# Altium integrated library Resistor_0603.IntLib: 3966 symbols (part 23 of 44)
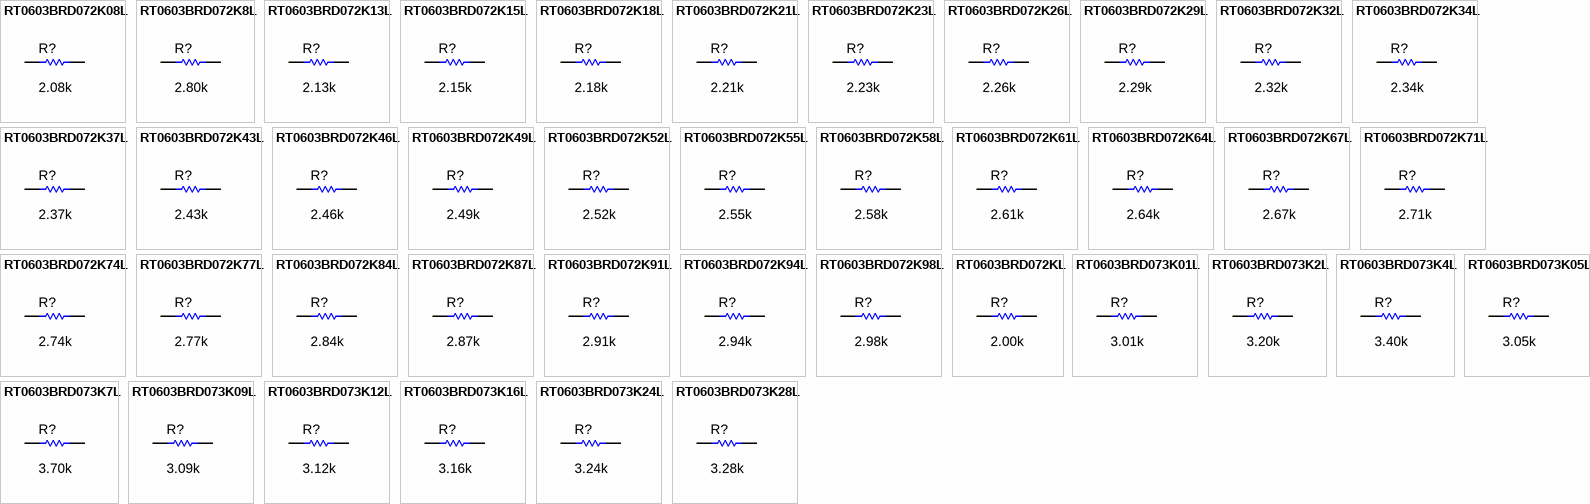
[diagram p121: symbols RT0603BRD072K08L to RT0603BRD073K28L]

## RT0603BRD072K98L
designator R?  ValueDisplayed: 2.98k  (hidden comment: RT0603BRD072K98L)
RES, 2.98 k, 0.1%, 0.1 W, 0603; Manufacturer: Yageo America; CompType: Resistor; Value: 2.98k; Res_ohm: 2980; Value_Code: 2k98; Tolerance_%: 0.1; Value2: 0.1W; VDC_V: 75; TempCo: 25 ppm/C; SizeArea_mm2: 1.28; SizeX_mm: 1.6; SizeY_mm: 0.8; SizeZ_mm: 1; EIA_Code: E192; U/M: EA; AEC Category: Q200
signal-integrity model Resistor
simulation model Resistor
footprint 0603
footprint 0603M
footprint 0603L
footprint 0603_HV
footprint 0603S
pins: 1, 2

## RT0603BRD072KL
designator R?  ValueDisplayed: 2.00k  (hidden comment: RT0603BRD072KL)
RES, 2.00 k, 0.1%, 0.1 W, 0603; Manufacturer: Yageo America; CompType: Resistor; Value: 2.00k; Res_ohm: 2000; Value_Code: 2k00; Tolerance_%: 0.1; Value2: 0.1W; VDC_V: 75; TempCo: 25 ppm/C; SizeArea_mm2: 1.28; SizeX_mm: 1.6; SizeY_mm: 0.8; SizeZ_mm: 1; EIA_Code: E192; U/M: EA; AEC Category: Q200
signal-integrity model Resistor
simulation model Resistor
footprint 0603
footprint 0603M
footprint 0603L
footprint 0603_HV
footprint 0603S
pins: 1, 2

## RT0603BRD073K01L
designator R?  ValueDisplayed: 3.01k  (hidden comment: RT0603BRD073K01L)
RES, 3.01 k, 0.1%, 0.1 W, 0603; Manufacturer: Yageo America; CompType: Resistor; Value: 3.01k; Res_ohm: 3010; Value_Code: 3k01; Tolerance_%: 0.1; Value2: 0.1W; VDC_V: 75; TempCo: 25 ppm/C; SizeArea_mm2: 1.28; SizeX_mm: 1.6; SizeY_mm: 0.8; SizeZ_mm: 1; EIA_Code: E192; U/M: EA; AEC Category: Q200; Green_Lifecycle: Active; Green_REACh: Passed
signal-integrity model Resistor
simulation model Resistor
footprint 0603
footprint 0603M
footprint 0603L
footprint 0603_HV
footprint 0603S
pins: 1, 2

## RT0603BRD073K2L
designator R?  ValueDisplayed: 3.20k  (hidden comment: RT0603BRD073K2L)
RES, 3.20 k, 0.1%, 0.1 W, 0603; Manufacturer: Yageo America; CompType: Resistor; Value: 3.20k; Res_ohm: 3200; Value_Code: 3k20; Tolerance_%: 0.1; Value2: 0.1W; VDC_V: 75; TempCo: 25 ppm/C; SizeArea_mm2: 1.28; SizeX_mm: 1.6; SizeY_mm: 0.8; SizeZ_mm: 1; EIA_Code: E192; U/M: EA; AEC Category: Q200
signal-integrity model Resistor
simulation model Resistor
footprint 0603
footprint 0603M
footprint 0603L
footprint 0603_HV
footprint 0603S
pins: 1, 2

## RT0603BRD073K4L
designator R?  ValueDisplayed: 3.40k  (hidden comment: RT0603BRD073K4L)
RES, 3.40 k, 0.1%, 0.1 W, 0603; Manufacturer: Yageo America; CompType: Resistor; Value: 3.40k; Res_ohm: 3400; Value_Code: 3k40; Tolerance_%: 0.1; Value2: 0.1W; VDC_V: 75; TempCo: 25 ppm/C; SizeArea_mm2: 1.28; SizeX_mm: 1.6; SizeY_mm: 0.8; SizeZ_mm: 1; EIA_Code: E192; U/M: EA; AEC Category: Q200
signal-integrity model Resistor
simulation model Resistor
footprint 0603
footprint 0603M
footprint 0603L
footprint 0603_HV
footprint 0603S
pins: 1, 2

## RT0603BRD073K05L
designator R?  ValueDisplayed: 3.05k  (hidden comment: RT0603BRD073K05L)
RES, 3.05 k, 0.1%, 0.1 W, 0603; Manufacturer: Yageo America; CompType: Resistor; Value: 3.05k; Res_ohm: 3050; Value_Code: 3k05; Tolerance_%: 0.1; Value2: 0.1W; VDC_V: 75; TempCo: 25 ppm/C; SizeArea_mm2: 1.28; SizeX_mm: 1.6; SizeY_mm: 0.8; SizeZ_mm: 1; EIA_Code: E192; U/M: EA; AEC Category: Q200
signal-integrity model Resistor
simulation model Resistor
footprint 0603
footprint 0603M
footprint 0603L
footprint 0603_HV
footprint 0603S
pins: 1, 2

## RT0603BRD073K7L
designator R?  ValueDisplayed: 3.70k  (hidden comment: RT0603BRD073K7L)
RES, 3.70 k, 0.1%, 0.1 W, 0603; Manufacturer: Yageo America; CompType: Resistor; Value: 3.70k; Res_ohm: 3700; Value_Code: 3k70; Tolerance_%: 0.1; Value2: 0.1W; VDC_V: 75; TempCo: 25 ppm/C; SizeArea_mm2: 1.28; SizeX_mm: 1.6; SizeY_mm: 0.8; SizeZ_mm: 1; EIA_Code: E192; U/M: EA; AEC Category: Q200
signal-integrity model Resistor
simulation model Resistor
footprint 0603
footprint 0603M
footprint 0603L
footprint 0603_HV
footprint 0603S
pins: 1, 2

## RT0603BRD073K09L
designator R?  ValueDisplayed: 3.09k  (hidden comment: RT0603BRD073K09L)
RES, 3.09 k, 0.1%, 0.1 W, 0603; Manufacturer: Yageo America; CompType: Resistor; Value: 3.09k; Res_ohm: 3090; Value_Code: 3k09; Tolerance_%: 0.1; Value2: 0.1W; VDC_V: 75; TempCo: 25 ppm/C; SizeArea_mm2: 1.28; SizeX_mm: 1.6; SizeY_mm: 0.8; SizeZ_mm: 1; EIA_Code: E192; U/M: EA; AEC Category: Q200
signal-integrity model Resistor
simulation model Resistor
footprint 0603
footprint 0603M
footprint 0603L
footprint 0603_HV
footprint 0603S
pins: 1, 2

## RT0603BRD073K12L
designator R?  ValueDisplayed: 3.12k  (hidden comment: RT0603BRD073K12L)
RES, 3.12 k, 0.1%, 0.1 W, 0603; Manufacturer: Yageo America; CompType: Resistor; Value: 3.12k; Res_ohm: 3120; Value_Code: 3k12; Tolerance_%: 0.1; Value2: 0.1W; VDC_V: 75; TempCo: 25 ppm/C; SizeArea_mm2: 1.28; SizeX_mm: 1.6; SizeY_mm: 0.8; SizeZ_mm: 1; EIA_Code: E192; U/M: EA; AEC Category: Q200
signal-integrity model Resistor
simulation model Resistor
footprint 0603
footprint 0603M
footprint 0603L
footprint 0603_HV
footprint 0603S
pins: 1, 2

## RT0603BRD073K16L
designator R?  ValueDisplayed: 3.16k  (hidden comment: RT0603BRD073K16L)
RES, 3.16 k, 0.1%, 0.1 W, 0603; Manufacturer: Yageo America; CompType: Resistor; Value: 3.16k; Res_ohm: 3160; Value_Code: 3k16; Tolerance_%: 0.1; Value2: 0.1W; VDC_V: 75; TempCo: 25 ppm/C; SizeArea_mm2: 1.28; SizeX_mm: 1.6; SizeY_mm: 0.8; SizeZ_mm: 1; EIA_Code: E192; U/M: EA; AEC Category: Q200
signal-integrity model Resistor
simulation model Resistor
footprint 0603
footprint 0603M
footprint 0603L
footprint 0603_HV
footprint 0603S
pins: 1, 2

## RT0603BRD073K24L
designator R?  ValueDisplayed: 3.24k  (hidden comment: RT0603BRD073K24L)
RES, 3.24 k, 0.1%, 0.1 W, 0603; Manufacturer: Yageo America; CompType: Resistor; Value: 3.24k; Res_ohm: 3240; Value_Code: 3k24; Tolerance_%: 0.1; Value2: 0.1W; VDC_V: 75; TempCo: 25 ppm/C; SizeArea_mm2: 1.28; SizeX_mm: 1.6; SizeY_mm: 0.8; SizeZ_mm: 1; EIA_Code: E192; U/M: EA; AEC Category: Q200
signal-integrity model Resistor
simulation model Resistor
footprint 0603
footprint 0603M
footprint 0603L
footprint 0603_HV
footprint 0603S
pins: 1, 2

## RT0603BRD073K28L
designator R?  ValueDisplayed: 3.28k  (hidden comment: RT0603BRD073K28L)
RES, 3.28 k, 0.1%, 0.1 W, 0603; Manufacturer: Yageo America; CompType: Resistor; Value: 3.28k; Res_ohm: 3280; Value_Code: 3k28; Tolerance_%: 0.1; Value2: 0.1W; VDC_V: 75; TempCo: 25 ppm/C; SizeArea_mm2: 1.28; SizeX_mm: 1.6; SizeY_mm: 0.8; SizeZ_mm: 1; EIA_Code: E192; U/M: EA; AEC Category: Q200
signal-integrity model Resistor
simulation model Resistor
footprint 0603
footprint 0603M
footprint 0603L
footprint 0603_HV
footprint 0603S
pins: 1, 2

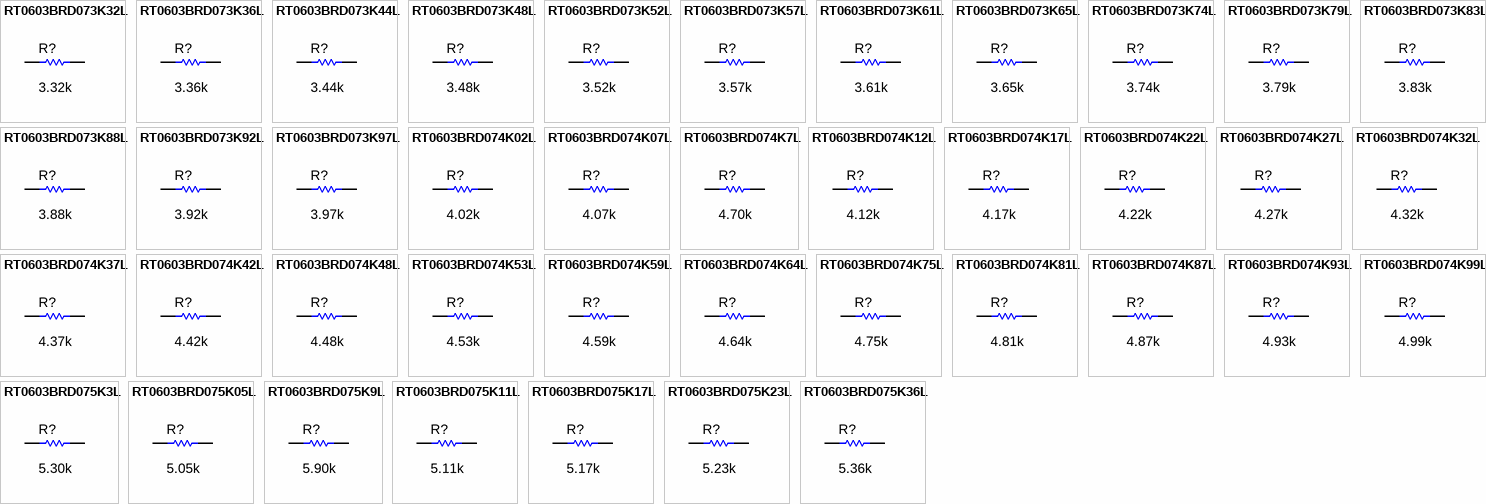
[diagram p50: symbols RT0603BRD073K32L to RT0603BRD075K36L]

## RT0603BRD073K32L
designator R?  ValueDisplayed: 3.32k  (hidden comment: RT0603BRD073K32L)
RES, 3.32 k, 0.1%, 0.1 W, 0603; Manufacturer: Yageo America; CompType: Resistor; Value: 3.32k; Res_ohm: 3320; Value_Code: 3k32; Tolerance_%: 0.1; Value2: 0.1W; VDC_V: 75; TempCo: 25 ppm/C; SizeArea_mm2: 1.28; SizeX_mm: 1.6; SizeY_mm: 0.8; SizeZ_mm: 1; EIA_Code: E192; U/M: EA; AEC Category: Q200
signal-integrity model Resistor
simulation model Resistor
footprint 0603
footprint 0603M
footprint 0603L
footprint 0603_HV
footprint 0603S
pins: 1, 2

## RT0603BRD073K36L
designator R?  ValueDisplayed: 3.36k  (hidden comment: RT0603BRD073K36L)
RES, 3.36 k, 0.1%, 0.1 W, 0603; Manufacturer: Yageo America; CompType: Resistor; Value: 3.36k; Res_ohm: 3360; Value_Code: 3k36; Tolerance_%: 0.1; Value2: 0.1W; VDC_V: 75; TempCo: 25 ppm/C; SizeArea_mm2: 1.28; SizeX_mm: 1.6; SizeY_mm: 0.8; SizeZ_mm: 1; EIA_Code: E192; U/M: EA; AEC Category: Q200
signal-integrity model Resistor
simulation model Resistor
footprint 0603
footprint 0603M
footprint 0603L
footprint 0603_HV
footprint 0603S
pins: 1, 2

## RT0603BRD073K44L
designator R?  ValueDisplayed: 3.44k  (hidden comment: RT0603BRD073K44L)
RES, 3.44 k, 0.1%, 0.1 W, 0603; Manufacturer: Yageo America; CompType: Resistor; Value: 3.44k; Res_ohm: 3440; Value_Code: 3k44; Tolerance_%: 0.1; Value2: 0.1W; VDC_V: 75; TempCo: 25 ppm/C; SizeArea_mm2: 1.28; SizeX_mm: 1.6; SizeY_mm: 0.8; SizeZ_mm: 1; EIA_Code: E192; U/M: EA; AEC Category: Q200
signal-integrity model Resistor
simulation model Resistor
footprint 0603
footprint 0603M
footprint 0603L
footprint 0603_HV
footprint 0603S
pins: 1, 2

## RT0603BRD073K48L
designator R?  ValueDisplayed: 3.48k  (hidden comment: RT0603BRD073K48L)
RES, 3.48 k, 0.1%, 0.1 W, 0603; Manufacturer: Yageo America; CompType: Resistor; Value: 3.48k; Res_ohm: 3480; Value_Code: 3k48; Tolerance_%: 0.1; Value2: 0.1W; VDC_V: 75; TempCo: 25 ppm/C; SizeArea_mm2: 1.28; SizeX_mm: 1.6; SizeY_mm: 0.8; SizeZ_mm: 1; EIA_Code: E192; U/M: EA; AEC Category: Q200
signal-integrity model Resistor
simulation model Resistor
footprint 0603
footprint 0603M
footprint 0603L
footprint 0603_HV
footprint 0603S
pins: 1, 2

## RT0603BRD073K52L
designator R?  ValueDisplayed: 3.52k  (hidden comment: RT0603BRD073K52L)
RES, 3.52 k, 0.1%, 0.1 W, 0603; Manufacturer: Yageo America; CompType: Resistor; Value: 3.52k; Res_ohm: 3520; Value_Code: 3k52; Tolerance_%: 0.1; Value2: 0.1W; VDC_V: 75; TempCo: 25 ppm/C; SizeArea_mm2: 1.28; SizeX_mm: 1.6; SizeY_mm: 0.8; SizeZ_mm: 1; EIA_Code: E192; U/M: EA; AEC Category: Q200
signal-integrity model Resistor
simulation model Resistor
footprint 0603
footprint 0603M
footprint 0603L
footprint 0603_HV
footprint 0603S
pins: 1, 2

## RT0603BRD073K57L
designator R?  ValueDisplayed: 3.57k  (hidden comment: RT0603BRD073K57L)
RES, 3.57 k, 0.1%, 0.1 W, 0603; Manufacturer: Yageo America; CompType: Resistor; Value: 3.57k; Res_ohm: 3570; Value_Code: 3k57; Tolerance_%: 0.1; Value2: 0.1W; VDC_V: 75; TempCo: 25 ppm/C; SizeArea_mm2: 1.28; SizeX_mm: 1.6; SizeY_mm: 0.8; SizeZ_mm: 1; EIA_Code: E192; U/M: EA; AEC Category: Q200
signal-integrity model Resistor
simulation model Resistor
footprint 0603
footprint 0603M
footprint 0603L
footprint 0603_HV
footprint 0603S
pins: 1, 2

## RT0603BRD073K61L
designator R?  ValueDisplayed: 3.61k  (hidden comment: RT0603BRD073K61L)
RES, 3.61 k, 0.1%, 0.1 W, 0603; Manufacturer: Yageo America; CompType: Resistor; Value: 3.61k; Res_ohm: 3610; Value_Code: 3k61; Tolerance_%: 0.1; Value2: 0.1W; VDC_V: 75; TempCo: 25 ppm/C; SizeArea_mm2: 1.28; SizeX_mm: 1.6; SizeY_mm: 0.8; SizeZ_mm: 1; EIA_Code: E192; U/M: EA; AEC Category: Q200
signal-integrity model Resistor
simulation model Resistor
footprint 0603
footprint 0603M
footprint 0603L
footprint 0603_HV
footprint 0603S
pins: 1, 2

## RT0603BRD073K65L
designator R?  ValueDisplayed: 3.65k  (hidden comment: RT0603BRD073K65L)
RES, 3.65 k, 0.1%, 0.1 W, 0603; Manufacturer: Yageo America; CompType: Resistor; Value: 3.65k; Res_ohm: 3650; Value_Code: 3k65; Tolerance_%: 0.1; Value2: 0.1W; VDC_V: 75; TempCo: 25 ppm/C; SizeArea_mm2: 1.28; SizeX_mm: 1.6; SizeY_mm: 0.8; SizeZ_mm: 1; EIA_Code: E192; U/M: EA; AEC Category: Q200
signal-integrity model Resistor
simulation model Resistor
footprint 0603
footprint 0603M
footprint 0603L
footprint 0603_HV
footprint 0603S
pins: 1, 2

## RT0603BRD073K74L
designator R?  ValueDisplayed: 3.74k  (hidden comment: RT0603BRD073K74L)
RES, 3.74 k, 0.1%, 0.1 W, 0603; Manufacturer: Yageo America; CompType: Resistor; Value: 3.74k; Res_ohm: 3740; Value_Code: 3k74; Tolerance_%: 0.1; Value2: 0.1W; VDC_V: 75; TempCo: 25 ppm/C; SizeArea_mm2: 1.28; SizeX_mm: 1.6; SizeY_mm: 0.8; SizeZ_mm: 1; EIA_Code: E192; U/M: EA; AEC Category: Q200
signal-integrity model Resistor
simulation model Resistor
footprint 0603
footprint 0603M
footprint 0603L
footprint 0603_HV
footprint 0603S
pins: 1, 2

## RT0603BRD073K79L
designator R?  ValueDisplayed: 3.79k  (hidden comment: RT0603BRD073K79L)
RES, 3.79 k, 0.1%, 0.1 W, 0603; Manufacturer: Yageo America; CompType: Resistor; Value: 3.79k; Res_ohm: 3790; Value_Code: 3k79; Tolerance_%: 0.1; Value2: 0.1W; VDC_V: 75; TempCo: 25 ppm/C; SizeArea_mm2: 1.28; SizeX_mm: 1.6; SizeY_mm: 0.8; SizeZ_mm: 1; EIA_Code: E192; U/M: EA; AEC Category: Q200
signal-integrity model Resistor
simulation model Resistor
footprint 0603
footprint 0603M
footprint 0603L
footprint 0603_HV
footprint 0603S
pins: 1, 2

## RT0603BRD073K83L
designator R?  ValueDisplayed: 3.83k  (hidden comment: RT0603BRD073K83L)
RES, 3.83 k, 0.1%, 0.1 W, 0603; Manufacturer: Yageo America; CompType: Resistor; Value: 3.83k; Res_ohm: 3830; Value_Code: 3k83; Tolerance_%: 0.1; Value2: 0.1W; VDC_V: 75; TempCo: 25 ppm/C; SizeArea_mm2: 1.28; SizeX_mm: 1.6; SizeY_mm: 0.8; SizeZ_mm: 1; EIA_Code: E192; U/M: EA; AEC Category: Q200
signal-integrity model Resistor
simulation model Resistor
footprint 0603
footprint 0603M
footprint 0603L
footprint 0603_HV
footprint 0603S
pins: 1, 2

## RT0603BRD073K88L
designator R?  ValueDisplayed: 3.88k  (hidden comment: RT0603BRD073K88L)
RES, 3.88 k, 0.1%, 0.1 W, 0603; Manufacturer: Yageo America; CompType: Resistor; Value: 3.88k; Res_ohm: 3880; Value_Code: 3k88; Tolerance_%: 0.1; Value2: 0.1W; VDC_V: 75; TempCo: 25 ppm/C; SizeArea_mm2: 1.28; SizeX_mm: 1.6; SizeY_mm: 0.8; SizeZ_mm: 1; EIA_Code: E192; U/M: EA; AEC Category: Q200
signal-integrity model Resistor
simulation model Resistor
footprint 0603
footprint 0603M
footprint 0603L
footprint 0603_HV
footprint 0603S
pins: 1, 2

## RT0603BRD073K92L
designator R?  ValueDisplayed: 3.92k  (hidden comment: RT0603BRD073K92L)
RES, 3.92 k, 0.1%, 0.1 W, 0603; Manufacturer: Yageo America; CompType: Resistor; Value: 3.92k; Res_ohm: 3920; Value_Code: 3k92; Tolerance_%: 0.1; Value2: 0.1W; VDC_V: 75; TempCo: 25 ppm/C; SizeArea_mm2: 1.28; SizeX_mm: 1.6; SizeY_mm: 0.8; SizeZ_mm: 1; EIA_Code: E192; U/M: EA; AEC Category: Q200
signal-integrity model Resistor
simulation model Resistor
footprint 0603
footprint 0603M
footprint 0603L
footprint 0603_HV
footprint 0603S
pins: 1, 2

## RT0603BRD073K97L
designator R?  ValueDisplayed: 3.97k  (hidden comment: RT0603BRD073K97L)
RES, 3.97 k, 0.1%, 0.1 W, 0603; Manufacturer: Yageo America; CompType: Resistor; Value: 3.97k; Res_ohm: 3970; Value_Code: 3k97; Tolerance_%: 0.1; Value2: 0.1W; VDC_V: 75; TempCo: 25 ppm/C; SizeArea_mm2: 1.28; SizeX_mm: 1.6; SizeY_mm: 0.8; SizeZ_mm: 1; EIA_Code: E192; U/M: EA; AEC Category: Q200
signal-integrity model Resistor
simulation model Resistor
footprint 0603
footprint 0603M
footprint 0603L
footprint 0603_HV
footprint 0603S
pins: 1, 2

## RT0603BRD074K02L
designator R?  ValueDisplayed: 4.02k  (hidden comment: RT0603BRD074K02L)
RES, 4.02 k, 0.1%, 0.1 W, 0603; Manufacturer: Yageo America; CompType: Resistor; Value: 4.02k; Res_ohm: 4020; Value_Code: 4k02; Tolerance_%: 0.1; Value2: 0.1W; VDC_V: 75; TempCo: 25 ppm/C; SizeArea_mm2: 1.28; SizeX_mm: 1.6; SizeY_mm: 0.8; SizeZ_mm: 1; EIA_Code: E192; U/M: EA; AEC Category: Q200
signal-integrity model Resistor
simulation model Resistor
footprint 0603
footprint 0603M
footprint 0603L
footprint 0603_HV
footprint 0603S
pins: 1, 2

## RT0603BRD074K07L
designator R?  ValueDisplayed: 4.07k  (hidden comment: RT0603BRD074K07L)
RES, 4.07 k, 0.1%, 0.1 W, 0603; Manufacturer: Yageo America; CompType: Resistor; Value: 4.07k; Res_ohm: 4070; Value_Code: 4k07; Tolerance_%: 0.1; Value2: 0.1W; VDC_V: 75; TempCo: 25 ppm/C; SizeArea_mm2: 1.28; SizeX_mm: 1.6; SizeY_mm: 0.8; SizeZ_mm: 1; EIA_Code: E192; U/M: EA; AEC Category: Q200
signal-integrity model Resistor
simulation model Resistor
footprint 0603
footprint 0603M
footprint 0603L
footprint 0603_HV
footprint 0603S
pins: 1, 2

## RT0603BRD074K7L
designator R?  ValueDisplayed: 4.70k  (hidden comment: RT0603BRD074K7L)
RES, 4.70 k, 0.1%, 0.1 W, 0603; Manufacturer: Yageo America; CompType: Resistor; Value: 4.70k; Res_ohm: 4700; Value_Code: 4k70; Tolerance_%: 0.1; Value2: 0.1W; VDC_V: 75; TempCo: 25 ppm/C; SizeArea_mm2: 1.28; SizeX_mm: 1.6; SizeY_mm: 0.8; SizeZ_mm: 1; EIA_Code: E192; U/M: EA; AEC Category: Q200
signal-integrity model Resistor
simulation model Resistor
footprint 0603
footprint 0603M
footprint 0603L
footprint 0603_HV
footprint 0603S
pins: 1, 2

## RT0603BRD074K12L
designator R?  ValueDisplayed: 4.12k  (hidden comment: RT0603BRD074K12L)
RES, 4.12 k, 0.1%, 0.1 W, 0603; Manufacturer: Yageo America; CompType: Resistor; Value: 4.12k; Res_ohm: 4120; Value_Code: 4k12; Tolerance_%: 0.1; Value2: 0.1W; VDC_V: 75; TempCo: 25 ppm/C; SizeArea_mm2: 1.28; SizeX_mm: 1.6; SizeY_mm: 0.8; SizeZ_mm: 1; EIA_Code: E192; U/M: EA; AEC Category: Q200
signal-integrity model Resistor
simulation model Resistor
footprint 0603
footprint 0603M
footprint 0603L
footprint 0603_HV
footprint 0603S
pins: 1, 2

## RT0603BRD074K17L
designator R?  ValueDisplayed: 4.17k  (hidden comment: RT0603BRD074K17L)
RES, 4.17 k, 0.1%, 0.1 W, 0603; Manufacturer: Yageo America; CompType: Resistor; Value: 4.17k; Res_ohm: 4170; Value_Code: 4k17; Tolerance_%: 0.1; Value2: 0.1W; VDC_V: 75; TempCo: 25 ppm/C; SizeArea_mm2: 1.28; SizeX_mm: 1.6; SizeY_mm: 0.8; SizeZ_mm: 1; EIA_Code: E192; U/M: EA; AEC Category: Q200
signal-integrity model Resistor
simulation model Resistor
footprint 0603
footprint 0603M
footprint 0603L
footprint 0603_HV
footprint 0603S
pins: 1, 2

## RT0603BRD074K22L
designator R?  ValueDisplayed: 4.22k  (hidden comment: RT0603BRD074K22L)
RES, 4.22 k, 0.1%, 0.1 W, 0603; Manufacturer: Yageo America; CompType: Resistor; Value: 4.22k; Res_ohm: 4220; Value_Code: 4k22; Tolerance_%: 0.1; Value2: 0.1W; VDC_V: 75; TempCo: 25 ppm/C; SizeArea_mm2: 1.28; SizeX_mm: 1.6; SizeY_mm: 0.8; SizeZ_mm: 1; EIA_Code: E192; U/M: EA; AEC Category: Q200
signal-integrity model Resistor
simulation model Resistor
footprint 0603
footprint 0603M
footprint 0603L
footprint 0603_HV
footprint 0603S
pins: 1, 2

## RT0603BRD074K27L
designator R?  ValueDisplayed: 4.27k  (hidden comment: RT0603BRD074K27L)
RES, 4.27 k, 0.1%, 0.1 W, 0603; Manufacturer: Yageo America; CompType: Resistor; Value: 4.27k; Res_ohm: 4270; Value_Code: 4k27; Tolerance_%: 0.1; Value2: 0.1W; VDC_V: 75; TempCo: 25 ppm/C; SizeArea_mm2: 1.28; SizeX_mm: 1.6; SizeY_mm: 0.8; SizeZ_mm: 1; EIA_Code: E192; U/M: EA; AEC Category: Q200
signal-integrity model Resistor
simulation model Resistor
footprint 0603
footprint 0603M
footprint 0603L
footprint 0603_HV
footprint 0603S
pins: 1, 2

## RT0603BRD074K32L
designator R?  ValueDisplayed: 4.32k  (hidden comment: RT0603BRD074K32L)
RES, 4.32 k, 0.1%, 0.1 W, 0603; Manufacturer: Yageo America; CompType: Resistor; Value: 4.32k; Res_ohm: 4320; Value_Code: 4k32; Tolerance_%: 0.1; Value2: 0.1W; VDC_V: 75; TempCo: 25 ppm/C; SizeArea_mm2: 1.28; SizeX_mm: 1.6; SizeY_mm: 0.8; SizeZ_mm: 1; EIA_Code: E192; U/M: EA; AEC Category: Q200
signal-integrity model Resistor
simulation model Resistor
footprint 0603
footprint 0603M
footprint 0603L
footprint 0603_HV
footprint 0603S
pins: 1, 2

## RT0603BRD074K37L
designator R?  ValueDisplayed: 4.37k  (hidden comment: RT0603BRD074K37L)
RES, 4.37 k, 0.1%, 0.1 W, 0603; Manufacturer: Yageo America; CompType: Resistor; Value: 4.37k; Res_ohm: 4370; Value_Code: 4k37; Tolerance_%: 0.1; Value2: 0.1W; VDC_V: 75; TempCo: 25 ppm/C; SizeArea_mm2: 1.28; SizeX_mm: 1.6; SizeY_mm: 0.8; SizeZ_mm: 1; EIA_Code: E192; U/M: EA; AEC Category: Q200
signal-integrity model Resistor
simulation model Resistor
footprint 0603
footprint 0603M
footprint 0603L
footprint 0603_HV
footprint 0603S
pins: 1, 2

## RT0603BRD074K42L
designator R?  ValueDisplayed: 4.42k  (hidden comment: RT0603BRD074K42L)
RES, 4.42 k, 0.1%, 0.1 W, 0603; Manufacturer: Yageo America; CompType: Resistor; Value: 4.42k; Res_ohm: 4420; Value_Code: 4k42; Tolerance_%: 0.1; Value2: 0.1W; VDC_V: 75; TempCo: 25 ppm/C; SizeArea_mm2: 1.28; SizeX_mm: 1.6; SizeY_mm: 0.8; SizeZ_mm: 1; EIA_Code: E192; U/M: EA; AEC Category: Q200
signal-integrity model Resistor
simulation model Resistor
footprint 0603
footprint 0603M
footprint 0603L
footprint 0603_HV
footprint 0603S
pins: 1, 2

## RT0603BRD074K48L
designator R?  ValueDisplayed: 4.48k  (hidden comment: RT0603BRD074K48L)
RES, 4.48 k, 0.1%, 0.1 W, 0603; Manufacturer: Yageo America; CompType: Resistor; Value: 4.48k; Res_ohm: 4480; Value_Code: 4k48; Tolerance_%: 0.1; Value2: 0.1W; VDC_V: 75; TempCo: 25 ppm/C; SizeArea_mm2: 1.28; SizeX_mm: 1.6; SizeY_mm: 0.8; SizeZ_mm: 1; EIA_Code: E192; U/M: EA; AEC Category: Q200
signal-integrity model Resistor
simulation model Resistor
footprint 0603
footprint 0603M
footprint 0603L
footprint 0603_HV
footprint 0603S
pins: 1, 2

## RT0603BRD074K53L
designator R?  ValueDisplayed: 4.53k  (hidden comment: RT0603BRD074K53L)
RES, 4.53 k, 0.1%, 0.1 W, 0603; Manufacturer: Yageo America; CompType: Resistor; Value: 4.53k; Res_ohm: 4530; Value_Code: 4k53; Tolerance_%: 0.1; Value2: 0.1W; VDC_V: 75; TempCo: 25 ppm/C; SizeArea_mm2: 1.28; SizeX_mm: 1.6; SizeY_mm: 0.8; SizeZ_mm: 1; EIA_Code: E192; U/M: EA; AEC Category: Q200
signal-integrity model Resistor
simulation model Resistor
footprint 0603
footprint 0603M
footprint 0603L
footprint 0603_HV
footprint 0603S
pins: 1, 2

## RT0603BRD074K59L
designator R?  ValueDisplayed: 4.59k  (hidden comment: RT0603BRD074K59L)
RES, 4.59 k, 0.1%, 0.1 W, 0603; Manufacturer: Yageo America; CompType: Resistor; Value: 4.59k; Res_ohm: 4590; Value_Code: 4k59; Tolerance_%: 0.1; Value2: 0.1W; VDC_V: 75; TempCo: 25 ppm/C; SizeArea_mm2: 1.28; SizeX_mm: 1.6; SizeY_mm: 0.8; SizeZ_mm: 1; EIA_Code: E192; U/M: EA; AEC Category: Q200
signal-integrity model Resistor
simulation model Resistor
footprint 0603
footprint 0603M
footprint 0603L
footprint 0603_HV
footprint 0603S
pins: 1, 2

## RT0603BRD074K64L
designator R?  ValueDisplayed: 4.64k  (hidden comment: RT0603BRD074K64L)
RES, 4.64 k, 0.1%, 0.1 W, 0603; Manufacturer: Yageo America; CompType: Resistor; Value: 4.64k; Res_ohm: 4640; Value_Code: 4k64; Tolerance_%: 0.1; Value2: 0.1W; VDC_V: 75; TempCo: 25 ppm/C; SizeArea_mm2: 1.28; SizeX_mm: 1.6; SizeY_mm: 0.8; SizeZ_mm: 1; EIA_Code: E192; U/M: EA; AEC Category: Q200
signal-integrity model Resistor
simulation model Resistor
footprint 0603
footprint 0603M
footprint 0603L
footprint 0603_HV
footprint 0603S
pins: 1, 2

## RT0603BRD074K75L
designator R?  ValueDisplayed: 4.75k  (hidden comment: RT0603BRD074K75L)
RES, 4.75 k, 0.1%, 0.1 W, 0603; Manufacturer: Yageo America; CompType: Resistor; Value: 4.75k; Res_ohm: 4750; Value_Code: 4k75; Tolerance_%: 0.1; Value2: 0.1W; VDC_V: 75; TempCo: 25 ppm/C; SizeArea_mm2: 1.28; SizeX_mm: 1.6; SizeY_mm: 0.8; SizeZ_mm: 1; EIA_Code: E192; U/M: EA; AEC Category: Q200
signal-integrity model Resistor
simulation model Resistor
footprint 0603
footprint 0603M
footprint 0603L
footprint 0603_HV
footprint 0603S
pins: 1, 2

## RT0603BRD074K81L
designator R?  ValueDisplayed: 4.81k  (hidden comment: RT0603BRD074K81L)
RES, 4.81 k, 0.1%, 0.1 W, 0603; Manufacturer: Yageo America; CompType: Resistor; Value: 4.81k; Res_ohm: 4810; Value_Code: 4k81; Tolerance_%: 0.1; Value2: 0.1W; VDC_V: 75; TempCo: 25 ppm/C; SizeArea_mm2: 1.28; SizeX_mm: 1.6; SizeY_mm: 0.8; SizeZ_mm: 1; EIA_Code: E192; U/M: EA; AEC Category: Q200
signal-integrity model Resistor
simulation model Resistor
footprint 0603
footprint 0603M
footprint 0603L
footprint 0603_HV
footprint 0603S
pins: 1, 2

## RT0603BRD074K87L
designator R?  ValueDisplayed: 4.87k  (hidden comment: RT0603BRD074K87L)
RES, 4.87 k, 0.1%, 0.1 W, 0603; Manufacturer: Yageo America; CompType: Resistor; Value: 4.87k; Res_ohm: 4870; Value_Code: 4k87; Tolerance_%: 0.1; Value2: 0.1W; VDC_V: 75; TempCo: 25 ppm/C; SizeArea_mm2: 1.28; SizeX_mm: 1.6; SizeY_mm: 0.8; SizeZ_mm: 1; EIA_Code: E192; U/M: EA; AEC Category: Q200
signal-integrity model Resistor
simulation model Resistor
footprint 0603
footprint 0603M
footprint 0603L
footprint 0603_HV
footprint 0603S
pins: 1, 2

## RT0603BRD074K93L
designator R?  ValueDisplayed: 4.93k  (hidden comment: RT0603BRD074K93L)
RES, 4.93 k, 0.1%, 0.1 W, 0603; Manufacturer: Yageo America; CompType: Resistor; Value: 4.93k; Res_ohm: 4930; Value_Code: 4k93; Tolerance_%: 0.1; Value2: 0.1W; VDC_V: 75; TempCo: 25 ppm/C; SizeArea_mm2: 1.28; SizeX_mm: 1.6; SizeY_mm: 0.8; SizeZ_mm: 1; EIA_Code: E192; U/M: EA; AEC Category: Q200
signal-integrity model Resistor
simulation model Resistor
footprint 0603
footprint 0603M
footprint 0603L
footprint 0603_HV
footprint 0603S
pins: 1, 2

## RT0603BRD074K99L
designator R?  ValueDisplayed: 4.99k  (hidden comment: RT0603BRD074K99L)
RES, 4.99 k, 0.1%, 0.1 W, 0603; Manufacturer: Yageo America; CompType: Resistor; Value: 4.99k; Res_ohm: 4990; Value_Code: 4k99; Tolerance_%: 0.1; Value2: 0.1W; VDC_V: 75; TempCo: 25 ppm/C; SizeArea_mm2: 1.28; SizeX_mm: 1.6; SizeY_mm: 0.8; SizeZ_mm: 1; EIA_Code: E192; U/M: EA; AEC Category: Q200
signal-integrity model Resistor
simulation model Resistor
footprint 0603
footprint 0603M
footprint 0603L
footprint 0603_HV
footprint 0603S
pins: 1, 2

## RT0603BRD075K3L
designator R?  ValueDisplayed: 5.30k  (hidden comment: RT0603BRD075K3L)
RES, 5.30 k, 0.1%, 0.1 W, 0603; Manufacturer: Yageo America; CompType: Resistor; Value: 5.30k; Res_ohm: 5300; Value_Code: 5k30; Tolerance_%: 0.1; Value2: 0.1W; VDC_V: 75; TempCo: 25 ppm/C; SizeArea_mm2: 1.28; SizeX_mm: 1.6; SizeY_mm: 0.8; SizeZ_mm: 1; EIA_Code: E192; U/M: EA; AEC Category: Q200
signal-integrity model Resistor
simulation model Resistor
footprint 0603
footprint 0603M
footprint 0603L
footprint 0603_HV
footprint 0603S
pins: 1, 2

## RT0603BRD075K05L
designator R?  ValueDisplayed: 5.05k  (hidden comment: RT0603BRD075K05L)
RES, 5.05 k, 0.1%, 0.1 W, 0603; Manufacturer: Yageo America; CompType: Resistor; Value: 5.05k; Res_ohm: 5050; Value_Code: 5k05; Tolerance_%: 0.1; Value2: 0.1W; VDC_V: 75; TempCo: 25 ppm/C; SizeArea_mm2: 1.28; SizeX_mm: 1.6; SizeY_mm: 0.8; SizeZ_mm: 1; EIA_Code: E192; U/M: EA; AEC Category: Q200
signal-integrity model Resistor
simulation model Resistor
footprint 0603
footprint 0603M
footprint 0603L
footprint 0603_HV
footprint 0603S
pins: 1, 2

## RT0603BRD075K9L
designator R?  ValueDisplayed: 5.90k  (hidden comment: RT0603BRD075K9L)
RES, 5.90 k, 0.1%, 0.1 W, 0603; Manufacturer: Yageo America; CompType: Resistor; Value: 5.90k; Res_ohm: 5900; Value_Code: 5k90; Tolerance_%: 0.1; Value2: 0.1W; VDC_V: 75; TempCo: 25 ppm/C; SizeArea_mm2: 1.28; SizeX_mm: 1.6; SizeY_mm: 0.8; SizeZ_mm: 1; EIA_Code: E192; U/M: EA; AEC Category: Q200
signal-integrity model Resistor
simulation model Resistor
footprint 0603
footprint 0603M
footprint 0603L
footprint 0603_HV
footprint 0603S
pins: 1, 2

## RT0603BRD075K11L
designator R?  ValueDisplayed: 5.11k  (hidden comment: RT0603BRD075K11L)
RES, 5.11 k, 0.1%, 0.1 W, 0603; Manufacturer: Yageo America; CompType: Resistor; Value: 5.11k; Res_ohm: 5110; Value_Code: 5k11; Tolerance_%: 0.1; Value2: 0.1W; VDC_V: 75; TempCo: 25 ppm/C; SizeArea_mm2: 1.28; SizeX_mm: 1.6; SizeY_mm: 0.8; SizeZ_mm: 1; EIA_Code: E192; U/M: EA; AEC Category: Q200
signal-integrity model Resistor
simulation model Resistor
footprint 0603
footprint 0603M
footprint 0603L
footprint 0603_HV
footprint 0603S
pins: 1, 2

## RT0603BRD075K17L
designator R?  ValueDisplayed: 5.17k  (hidden comment: RT0603BRD075K17L)
RES, 5.17 k, 0.1%, 0.1 W, 0603; Manufacturer: Yageo America; CompType: Resistor; Value: 5.17k; Res_ohm: 5170; Value_Code: 5k17; Tolerance_%: 0.1; Value2: 0.1W; VDC_V: 75; TempCo: 25 ppm/C; SizeArea_mm2: 1.28; SizeX_mm: 1.6; SizeY_mm: 0.8; SizeZ_mm: 1; EIA_Code: E192; U/M: EA; AEC Category: Q200
signal-integrity model Resistor
simulation model Resistor
footprint 0603
footprint 0603M
footprint 0603L
footprint 0603_HV
footprint 0603S
pins: 1, 2

## RT0603BRD075K23L
designator R?  ValueDisplayed: 5.23k  (hidden comment: RT0603BRD075K23L)
RES, 5.23 k, 0.1%, 0.1 W, 0603; Manufacturer: Yageo America; CompType: Resistor; Value: 5.23k; Res_ohm: 5230; Value_Code: 5k23; Tolerance_%: 0.1; Value2: 0.1W; VDC_V: 75; TempCo: 25 ppm/C; SizeArea_mm2: 1.28; SizeX_mm: 1.6; SizeY_mm: 0.8; SizeZ_mm: 1; EIA_Code: E192; U/M: EA; AEC Category: Q200
signal-integrity model Resistor
simulation model Resistor
footprint 0603
footprint 0603M
footprint 0603L
footprint 0603_HV
footprint 0603S
pins: 1, 2

## RT0603BRD075K36L
designator R?  ValueDisplayed: 5.36k  (hidden comment: RT0603BRD075K36L)
RES, 5.36 k, 0.1%, 0.1 W, 0603; Manufacturer: Yageo America; CompType: Resistor; Value: 5.36k; Res_ohm: 5360; Value_Code: 5k36; Tolerance_%: 0.1; Value2: 0.1W; VDC_V: 75; TempCo: 25 ppm/C; SizeArea_mm2: 1.28; SizeX_mm: 1.6; SizeY_mm: 0.8; SizeZ_mm: 1; EIA_Code: E192; U/M: EA; AEC Category: Q200
signal-integrity model Resistor
simulation model Resistor
footprint 0603
footprint 0603M
footprint 0603L
footprint 0603_HV
footprint 0603S
pins: 1, 2

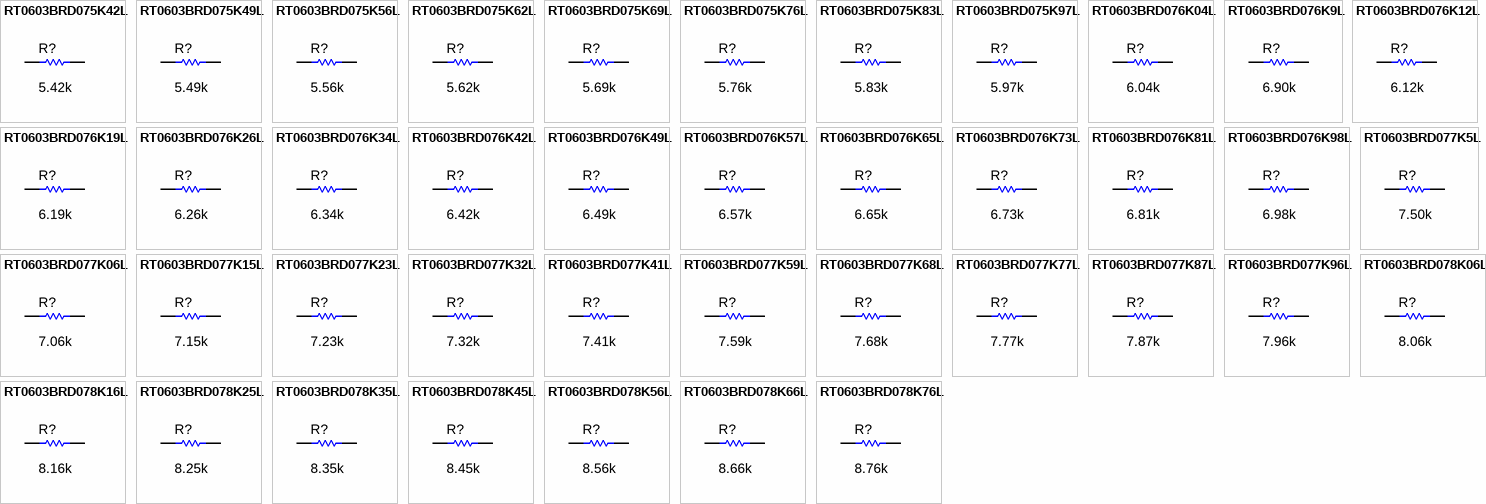
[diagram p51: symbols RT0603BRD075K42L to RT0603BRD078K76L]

## RT0603BRD075K42L
designator R?  ValueDisplayed: 5.42k  (hidden comment: RT0603BRD075K42L)
RES, 5.42 k, 0.1%, 0.1 W, 0603; Manufacturer: Yageo America; CompType: Resistor; Value: 5.42k; Res_ohm: 5420; Value_Code: 5k42; Tolerance_%: 0.1; Value2: 0.1W; VDC_V: 75; TempCo: 25 ppm/C; SizeArea_mm2: 1.28; SizeX_mm: 1.6; SizeY_mm: 0.8; SizeZ_mm: 1; EIA_Code: E192; U/M: EA; AEC Category: Q200
signal-integrity model Resistor
simulation model Resistor
footprint 0603
footprint 0603M
footprint 0603L
footprint 0603_HV
footprint 0603S
pins: 1, 2

## RT0603BRD075K49L
designator R?  ValueDisplayed: 5.49k  (hidden comment: RT0603BRD075K49L)
RES, 5.49 k, 0.1%, 0.1 W, 0603; Manufacturer: Yageo America; CompType: Resistor; Value: 5.49k; Res_ohm: 5490; Value_Code: 5k49; Tolerance_%: 0.1; Value2: 0.1W; VDC_V: 75; TempCo: 25 ppm/C; SizeArea_mm2: 1.28; SizeX_mm: 1.6; SizeY_mm: 0.8; SizeZ_mm: 1; EIA_Code: E192; U/M: EA; AEC Category: Q200
signal-integrity model Resistor
simulation model Resistor
footprint 0603
footprint 0603M
footprint 0603L
footprint 0603_HV
footprint 0603S
pins: 1, 2

## RT0603BRD075K56L
designator R?  ValueDisplayed: 5.56k  (hidden comment: RT0603BRD075K56L)
RES, 5.56 k, 0.1%, 0.1 W, 0603; Manufacturer: Yageo America; CompType: Resistor; Value: 5.56k; Res_ohm: 5560; Value_Code: 5k56; Tolerance_%: 0.1; Value2: 0.1W; VDC_V: 75; TempCo: 25 ppm/C; SizeArea_mm2: 1.28; SizeX_mm: 1.6; SizeY_mm: 0.8; SizeZ_mm: 1; EIA_Code: E192; U/M: EA; AEC Category: Q200
signal-integrity model Resistor
simulation model Resistor
footprint 0603
footprint 0603M
footprint 0603L
footprint 0603_HV
footprint 0603S
pins: 1, 2

## RT0603BRD075K62L
designator R?  ValueDisplayed: 5.62k  (hidden comment: RT0603BRD075K62L)
RES, 5.62 k, 0.1%, 0.1 W, 0603; Manufacturer: Yageo America; CompType: Resistor; Value: 5.62k; Res_ohm: 5620; Value_Code: 5k62; Tolerance_%: 0.1; Value2: 0.1W; VDC_V: 75; TempCo: 25 ppm/C; SizeArea_mm2: 1.28; SizeX_mm: 1.6; SizeY_mm: 0.8; SizeZ_mm: 1; EIA_Code: E192; U/M: EA; AEC Category: Q200
signal-integrity model Resistor
simulation model Resistor
footprint 0603
footprint 0603M
footprint 0603L
footprint 0603_HV
footprint 0603S
pins: 1, 2

## RT0603BRD075K69L
designator R?  ValueDisplayed: 5.69k  (hidden comment: RT0603BRD075K69L)
RES, 5.69 k, 0.1%, 0.1 W, 0603; Manufacturer: Yageo America; CompType: Resistor; Value: 5.69k; Res_ohm: 5690; Value_Code: 5k69; Tolerance_%: 0.1; Value2: 0.1W; VDC_V: 75; TempCo: 25 ppm/C; SizeArea_mm2: 1.28; SizeX_mm: 1.6; SizeY_mm: 0.8; SizeZ_mm: 1; EIA_Code: E192; U/M: EA; AEC Category: Q200
signal-integrity model Resistor
simulation model Resistor
footprint 0603
footprint 0603M
footprint 0603L
footprint 0603_HV
footprint 0603S
pins: 1, 2

## RT0603BRD075K76L
designator R?  ValueDisplayed: 5.76k  (hidden comment: RT0603BRD075K76L)
RES, 5.76 k, 0.1%, 0.1 W, 0603; Manufacturer: Yageo America; CompType: Resistor; Value: 5.76k; Res_ohm: 5760; Value_Code: 5k76; Tolerance_%: 0.1; Value2: 0.1W; VDC_V: 75; TempCo: 25 ppm/C; SizeArea_mm2: 1.28; SizeX_mm: 1.6; SizeY_mm: 0.8; SizeZ_mm: 1; EIA_Code: E192; U/M: EA; AEC Category: Q200
signal-integrity model Resistor
simulation model Resistor
footprint 0603
footprint 0603M
footprint 0603L
footprint 0603_HV
footprint 0603S
pins: 1, 2

## RT0603BRD075K83L
designator R?  ValueDisplayed: 5.83k  (hidden comment: RT0603BRD075K83L)
RES, 5.83 k, 0.1%, 0.1 W, 0603; Manufacturer: Yageo America; CompType: Resistor; Value: 5.83k; Res_ohm: 5830; Value_Code: 5k83; Tolerance_%: 0.1; Value2: 0.1W; VDC_V: 75; TempCo: 25 ppm/C; SizeArea_mm2: 1.28; SizeX_mm: 1.6; SizeY_mm: 0.8; SizeZ_mm: 1; EIA_Code: E192; U/M: EA; AEC Category: Q200
signal-integrity model Resistor
simulation model Resistor
footprint 0603
footprint 0603M
footprint 0603L
footprint 0603_HV
footprint 0603S
pins: 1, 2

## RT0603BRD075K97L
designator R?  ValueDisplayed: 5.97k  (hidden comment: RT0603BRD075K97L)
RES, 5.97 k, 0.1%, 0.1 W, 0603; Manufacturer: Yageo America; CompType: Resistor; Value: 5.97k; Res_ohm: 5970; Value_Code: 5k97; Tolerance_%: 0.1; Value2: 0.1W; VDC_V: 75; TempCo: 25 ppm/C; SizeArea_mm2: 1.28; SizeX_mm: 1.6; SizeY_mm: 0.8; SizeZ_mm: 1; EIA_Code: E192; U/M: EA; AEC Category: Q200
signal-integrity model Resistor
simulation model Resistor
footprint 0603
footprint 0603M
footprint 0603L
footprint 0603_HV
footprint 0603S
pins: 1, 2

## RT0603BRD076K04L
designator R?  ValueDisplayed: 6.04k  (hidden comment: RT0603BRD076K04L)
RES, 6.04 k, 0.1%, 0.1 W, 0603; Manufacturer: Yageo America; CompType: Resistor; Value: 6.04k; Res_ohm: 6040; Value_Code: 6k04; Tolerance_%: 0.1; Value2: 0.1W; VDC_V: 75; TempCo: 25 ppm/C; SizeArea_mm2: 1.28; SizeX_mm: 1.6; SizeY_mm: 0.8; SizeZ_mm: 1; EIA_Code: E192; U/M: EA; AEC Category: Q200
signal-integrity model Resistor
simulation model Resistor
footprint 0603
footprint 0603M
footprint 0603L
footprint 0603_HV
footprint 0603S
pins: 1, 2

## RT0603BRD076K9L
designator R?  ValueDisplayed: 6.90k  (hidden comment: RT0603BRD076K9L)
RES, 6.90 k, 0.1%, 0.1 W, 0603; Manufacturer: Yageo America; CompType: Resistor; Value: 6.90k; Res_ohm: 6900; Value_Code: 6k90; Tolerance_%: 0.1; Value2: 0.1W; VDC_V: 75; TempCo: 25 ppm/C; SizeArea_mm2: 1.28; SizeX_mm: 1.6; SizeY_mm: 0.8; SizeZ_mm: 1; EIA_Code: E192; U/M: EA; AEC Category: Q200
signal-integrity model Resistor
simulation model Resistor
footprint 0603
footprint 0603M
footprint 0603L
footprint 0603_HV
footprint 0603S
pins: 1, 2

## RT0603BRD076K12L
designator R?  ValueDisplayed: 6.12k  (hidden comment: RT0603BRD076K12L)
RES, 6.12 k, 0.1%, 0.1 W, 0603; Manufacturer: Yageo America; CompType: Resistor; Value: 6.12k; Res_ohm: 6120; Value_Code: 6k12; Tolerance_%: 0.1; Value2: 0.1W; VDC_V: 75; TempCo: 25 ppm/C; SizeArea_mm2: 1.28; SizeX_mm: 1.6; SizeY_mm: 0.8; SizeZ_mm: 1; EIA_Code: E192; U/M: EA; AEC Category: Q200
signal-integrity model Resistor
simulation model Resistor
footprint 0603
footprint 0603M
footprint 0603L
footprint 0603_HV
footprint 0603S
pins: 1, 2

## RT0603BRD076K19L
designator R?  ValueDisplayed: 6.19k  (hidden comment: RT0603BRD076K19L)
RES, 6.19 k, 0.1%, 0.1 W, 0603; Manufacturer: Yageo America; CompType: Resistor; Value: 6.19k; Res_ohm: 6190; Value_Code: 6k19; Tolerance_%: 0.1; Value2: 0.1W; VDC_V: 75; TempCo: 25 ppm/C; SizeArea_mm2: 1.28; SizeX_mm: 1.6; SizeY_mm: 0.8; SizeZ_mm: 1; EIA_Code: E192; U/M: EA; AEC Category: Q200
signal-integrity model Resistor
simulation model Resistor
footprint 0603
footprint 0603M
footprint 0603L
footprint 0603_HV
footprint 0603S
pins: 1, 2

## RT0603BRD076K26L
designator R?  ValueDisplayed: 6.26k  (hidden comment: RT0603BRD076K26L)
RES, 6.26 k, 0.1%, 0.1 W, 0603; Manufacturer: Yageo America; CompType: Resistor; Value: 6.26k; Res_ohm: 6260; Value_Code: 6k26; Tolerance_%: 0.1; Value2: 0.1W; VDC_V: 75; TempCo: 25 ppm/C; SizeArea_mm2: 1.28; SizeX_mm: 1.6; SizeY_mm: 0.8; SizeZ_mm: 1; EIA_Code: E192; U/M: EA; AEC Category: Q200
signal-integrity model Resistor
simulation model Resistor
footprint 0603
footprint 0603M
footprint 0603L
footprint 0603_HV
footprint 0603S
pins: 1, 2

## RT0603BRD076K34L
designator R?  ValueDisplayed: 6.34k  (hidden comment: RT0603BRD076K34L)
RES, 6.34 k, 0.1%, 0.1 W, 0603; Manufacturer: Yageo America; CompType: Resistor; Value: 6.34k; Res_ohm: 6340; Value_Code: 6k34; Tolerance_%: 0.1; Value2: 0.1W; VDC_V: 75; TempCo: 25 ppm/C; SizeArea_mm2: 1.28; SizeX_mm: 1.6; SizeY_mm: 0.8; SizeZ_mm: 1; EIA_Code: E192; U/M: EA; AEC Category: Q200
signal-integrity model Resistor
simulation model Resistor
footprint 0603
footprint 0603M
footprint 0603L
footprint 0603_HV
footprint 0603S
pins: 1, 2

## RT0603BRD076K42L
designator R?  ValueDisplayed: 6.42k  (hidden comment: RT0603BRD076K42L)
RES, 6.42 k, 0.1%, 0.1 W, 0603; Manufacturer: Yageo America; CompType: Resistor; Value: 6.42k; Res_ohm: 6420; Value_Code: 6k42; Tolerance_%: 0.1; Value2: 0.1W; VDC_V: 75; TempCo: 25 ppm/C; SizeArea_mm2: 1.28; SizeX_mm: 1.6; SizeY_mm: 0.8; SizeZ_mm: 1; EIA_Code: E192; U/M: EA; AEC Category: Q200
signal-integrity model Resistor
simulation model Resistor
footprint 0603
footprint 0603M
footprint 0603L
footprint 0603_HV
footprint 0603S
pins: 1, 2

## RT0603BRD076K49L
designator R?  ValueDisplayed: 6.49k  (hidden comment: RT0603BRD076K49L)
RES, 6.49 k, 0.1%, 0.1 W, 0603; Manufacturer: Yageo America; CompType: Resistor; Value: 6.49k; Res_ohm: 6490; Value_Code: 6k49; Tolerance_%: 0.1; Value2: 0.1W; VDC_V: 75; TempCo: 25 ppm/C; SizeArea_mm2: 1.28; SizeX_mm: 1.6; SizeY_mm: 0.8; SizeZ_mm: 1; EIA_Code: E192; U/M: EA; AEC Category: Q200
signal-integrity model Resistor
simulation model Resistor
footprint 0603
footprint 0603M
footprint 0603L
footprint 0603_HV
footprint 0603S
pins: 1, 2

## RT0603BRD076K57L
designator R?  ValueDisplayed: 6.57k  (hidden comment: RT0603BRD076K57L)
RES, 6.57 k, 0.1%, 0.1 W, 0603; Manufacturer: Yageo America; CompType: Resistor; Value: 6.57k; Res_ohm: 6570; Value_Code: 6k57; Tolerance_%: 0.1; Value2: 0.1W; VDC_V: 75; TempCo: 25 ppm/C; SizeArea_mm2: 1.28; SizeX_mm: 1.6; SizeY_mm: 0.8; SizeZ_mm: 1; EIA_Code: E192; U/M: EA; AEC Category: Q200
signal-integrity model Resistor
simulation model Resistor
footprint 0603
footprint 0603M
footprint 0603L
footprint 0603_HV
footprint 0603S
pins: 1, 2

## RT0603BRD076K65L
designator R?  ValueDisplayed: 6.65k  (hidden comment: RT0603BRD076K65L)
RES, 6.65 k, 0.1%, 0.1 W, 0603; Manufacturer: Yageo America; CompType: Resistor; Value: 6.65k; Res_ohm: 6650; Value_Code: 6k65; Tolerance_%: 0.1; Value2: 0.1W; VDC_V: 75; TempCo: 25 ppm/C; SizeArea_mm2: 1.28; SizeX_mm: 1.6; SizeY_mm: 0.8; SizeZ_mm: 1; EIA_Code: E192; U/M: EA; AEC Category: Q200
signal-integrity model Resistor
simulation model Resistor
footprint 0603
footprint 0603M
footprint 0603L
footprint 0603_HV
footprint 0603S
pins: 1, 2

## RT0603BRD076K73L
designator R?  ValueDisplayed: 6.73k  (hidden comment: RT0603BRD076K73L)
RES, 6.73 k, 0.1%, 0.1 W, 0603; Manufacturer: Yageo America; CompType: Resistor; Value: 6.73k; Res_ohm: 6730; Value_Code: 6k73; Tolerance_%: 0.1; Value2: 0.1W; VDC_V: 75; TempCo: 25 ppm/C; SizeArea_mm2: 1.28; SizeX_mm: 1.6; SizeY_mm: 0.8; SizeZ_mm: 1; EIA_Code: E192; U/M: EA; AEC Category: Q200
signal-integrity model Resistor
simulation model Resistor
footprint 0603
footprint 0603M
footprint 0603L
footprint 0603_HV
footprint 0603S
pins: 1, 2

## RT0603BRD076K81L
designator R?  ValueDisplayed: 6.81k  (hidden comment: RT0603BRD076K81L)
RES, 6.81 k, 0.1%, 0.1 W, 0603; Manufacturer: Yageo America; CompType: Resistor; Value: 6.81k; Res_ohm: 6810; Value_Code: 6k81; Tolerance_%: 0.1; Value2: 0.1W; VDC_V: 75; TempCo: 25 ppm/C; SizeArea_mm2: 1.28; SizeX_mm: 1.6; SizeY_mm: 0.8; SizeZ_mm: 1; EIA_Code: E192; U/M: EA; AEC Category: Q200
signal-integrity model Resistor
simulation model Resistor
footprint 0603
footprint 0603M
footprint 0603L
footprint 0603_HV
footprint 0603S
pins: 1, 2

## RT0603BRD076K98L
designator R?  ValueDisplayed: 6.98k  (hidden comment: RT0603BRD076K98L)
RES, 6.98 k, 0.1%, 0.1 W, 0603; Manufacturer: Yageo America; CompType: Resistor; Value: 6.98k; Res_ohm: 6980; Value_Code: 6k98; Tolerance_%: 0.1; Value2: 0.1W; VDC_V: 75; TempCo: 25 ppm/C; SizeArea_mm2: 1.28; SizeX_mm: 1.6; SizeY_mm: 0.8; SizeZ_mm: 1; EIA_Code: E192; U/M: EA; AEC Category: Q200
signal-integrity model Resistor
simulation model Resistor
footprint 0603
footprint 0603M
footprint 0603L
footprint 0603_HV
footprint 0603S
pins: 1, 2

## RT0603BRD077K5L
designator R?  ValueDisplayed: 7.50k  (hidden comment: RT0603BRD077K5L)
RES, 7.50 k, 0.1%, 0.1 W, 0603; Manufacturer: Yageo America; CompType: Resistor; Value: 7.50k; Res_ohm: 7500; Value_Code: 7k50; Tolerance_%: 0.1; Value2: 0.1W; VDC_V: 75; TempCo: 25 ppm/C; SizeArea_mm2: 1.28; SizeX_mm: 1.6; SizeY_mm: 0.8; SizeZ_mm: 1; EIA_Code: E192; U/M: EA; AEC Category: Q200
signal-integrity model Resistor
simulation model Resistor
footprint 0603
footprint 0603M
footprint 0603L
footprint 0603_HV
footprint 0603S
pins: 1, 2

## RT0603BRD077K06L
designator R?  ValueDisplayed: 7.06k  (hidden comment: RT0603BRD077K06L)
RES, 7.06 k, 0.1%, 0.1 W, 0603; Manufacturer: Yageo America; CompType: Resistor; Value: 7.06k; Res_ohm: 7060; Value_Code: 7k06; Tolerance_%: 0.1; Value2: 0.1W; VDC_V: 75; TempCo: 25 ppm/C; SizeArea_mm2: 1.28; SizeX_mm: 1.6; SizeY_mm: 0.8; SizeZ_mm: 1; EIA_Code: E192; U/M: EA; AEC Category: Q200
signal-integrity model Resistor
simulation model Resistor
footprint 0603
footprint 0603M
footprint 0603L
footprint 0603_HV
footprint 0603S
pins: 1, 2

## RT0603BRD077K15L
designator R?  ValueDisplayed: 7.15k  (hidden comment: RT0603BRD077K15L)
RES, 7.15 k, 0.1%, 0.1 W, 0603; Manufacturer: Yageo America; CompType: Resistor; Value: 7.15k; Res_ohm: 7150; Value_Code: 7k15; Tolerance_%: 0.1; Value2: 0.1W; VDC_V: 75; TempCo: 25 ppm/C; SizeArea_mm2: 1.28; SizeX_mm: 1.6; SizeY_mm: 0.8; SizeZ_mm: 1; EIA_Code: E192; U/M: EA; AEC Category: Q200
signal-integrity model Resistor
simulation model Resistor
footprint 0603
footprint 0603M
footprint 0603L
footprint 0603_HV
footprint 0603S
pins: 1, 2

## RT0603BRD077K23L
designator R?  ValueDisplayed: 7.23k  (hidden comment: RT0603BRD077K23L)
RES, 7.23 k, 0.1%, 0.1 W, 0603; Manufacturer: Yageo America; CompType: Resistor; Value: 7.23k; Res_ohm: 7230; Value_Code: 7k23; Tolerance_%: 0.1; Value2: 0.1W; VDC_V: 75; TempCo: 25 ppm/C; SizeArea_mm2: 1.28; SizeX_mm: 1.6; SizeY_mm: 0.8; SizeZ_mm: 1; EIA_Code: E192; U/M: EA; AEC Category: Q200
signal-integrity model Resistor
simulation model Resistor
footprint 0603
footprint 0603M
footprint 0603L
footprint 0603_HV
footprint 0603S
pins: 1, 2

## RT0603BRD077K32L
designator R?  ValueDisplayed: 7.32k  (hidden comment: RT0603BRD077K32L)
RES, 7.32 k, 0.1%, 0.1 W, 0603; Manufacturer: Yageo America; CompType: Resistor; Value: 7.32k; Res_ohm: 7320; Value_Code: 7k32; Tolerance_%: 0.1; Value2: 0.1W; VDC_V: 75; TempCo: 25 ppm/C; SizeArea_mm2: 1.28; SizeX_mm: 1.6; SizeY_mm: 0.8; SizeZ_mm: 1; EIA_Code: E192; U/M: EA; AEC Category: Q200
signal-integrity model Resistor
simulation model Resistor
footprint 0603
footprint 0603M
footprint 0603L
footprint 0603_HV
footprint 0603S
pins: 1, 2

## RT0603BRD077K41L
designator R?  ValueDisplayed: 7.41k  (hidden comment: RT0603BRD077K41L)
RES, 7.41 k, 0.1%, 0.1 W, 0603; Manufacturer: Yageo America; CompType: Resistor; Value: 7.41k; Res_ohm: 7410; Value_Code: 7k41; Tolerance_%: 0.1; Value2: 0.1W; VDC_V: 75; TempCo: 25 ppm/C; SizeArea_mm2: 1.28; SizeX_mm: 1.6; SizeY_mm: 0.8; SizeZ_mm: 1; EIA_Code: E192; U/M: EA; AEC Category: Q200
signal-integrity model Resistor
simulation model Resistor
footprint 0603
footprint 0603M
footprint 0603L
footprint 0603_HV
footprint 0603S
pins: 1, 2

## RT0603BRD077K59L
designator R?  ValueDisplayed: 7.59k  (hidden comment: RT0603BRD077K59L)
RES, 7.59 k, 0.1%, 0.1 W, 0603; Manufacturer: Yageo America; CompType: Resistor; Value: 7.59k; Res_ohm: 7590; Value_Code: 7k59; Tolerance_%: 0.1; Value2: 0.1W; VDC_V: 75; TempCo: 25 ppm/C; SizeArea_mm2: 1.28; SizeX_mm: 1.6; SizeY_mm: 0.8; SizeZ_mm: 1; EIA_Code: E192; U/M: EA; AEC Category: Q200
signal-integrity model Resistor
simulation model Resistor
footprint 0603
footprint 0603M
footprint 0603L
footprint 0603_HV
footprint 0603S
pins: 1, 2

## RT0603BRD077K68L
designator R?  ValueDisplayed: 7.68k  (hidden comment: RT0603BRD077K68L)
RES, 7.68 k, 0.1%, 0.1 W, 0603; Manufacturer: Yageo America; CompType: Resistor; Value: 7.68k; Res_ohm: 7680; Value_Code: 7k68; Tolerance_%: 0.1; Value2: 0.1W; VDC_V: 75; TempCo: 25 ppm/C; SizeArea_mm2: 1.28; SizeX_mm: 1.6; SizeY_mm: 0.8; SizeZ_mm: 1; EIA_Code: E192; U/M: EA; AEC Category: Q200
signal-integrity model Resistor
simulation model Resistor
footprint 0603
footprint 0603M
footprint 0603L
footprint 0603_HV
footprint 0603S
pins: 1, 2

## RT0603BRD077K77L
designator R?  ValueDisplayed: 7.77k  (hidden comment: RT0603BRD077K77L)
RES, 7.77 k, 0.1%, 0.1 W, 0603; Manufacturer: Yageo America; CompType: Resistor; Value: 7.77k; Res_ohm: 7770; Value_Code: 7k77; Tolerance_%: 0.1; Value2: 0.1W; VDC_V: 75; TempCo: 25 ppm/C; SizeArea_mm2: 1.28; SizeX_mm: 1.6; SizeY_mm: 0.8; SizeZ_mm: 1; EIA_Code: E192; U/M: EA; AEC Category: Q200
signal-integrity model Resistor
simulation model Resistor
footprint 0603
footprint 0603M
footprint 0603L
footprint 0603_HV
footprint 0603S
pins: 1, 2

## RT0603BRD077K87L
designator R?  ValueDisplayed: 7.87k  (hidden comment: RT0603BRD077K87L)
RES, 7.87 k, 0.1%, 0.1 W, 0603; Manufacturer: Yageo America; CompType: Resistor; Value: 7.87k; Res_ohm: 7870; Value_Code: 7k87; Tolerance_%: 0.1; Value2: 0.1W; VDC_V: 75; TempCo: 25 ppm/C; SizeArea_mm2: 1.28; SizeX_mm: 1.6; SizeY_mm: 0.8; SizeZ_mm: 1; EIA_Code: E192; U/M: EA; AEC Category: Q200
signal-integrity model Resistor
simulation model Resistor
footprint 0603
footprint 0603M
footprint 0603L
footprint 0603_HV
footprint 0603S
pins: 1, 2

## RT0603BRD077K96L
designator R?  ValueDisplayed: 7.96k  (hidden comment: RT0603BRD077K96L)
RES, 7.96 k, 0.1%, 0.1 W, 0603; Manufacturer: Yageo America; CompType: Resistor; Value: 7.96k; Res_ohm: 7960; Value_Code: 7k96; Tolerance_%: 0.1; Value2: 0.1W; VDC_V: 75; TempCo: 25 ppm/C; SizeArea_mm2: 1.28; SizeX_mm: 1.6; SizeY_mm: 0.8; SizeZ_mm: 1; EIA_Code: E192; U/M: EA; AEC Category: Q200
signal-integrity model Resistor
simulation model Resistor
footprint 0603
footprint 0603M
footprint 0603L
footprint 0603_HV
footprint 0603S
pins: 1, 2

## RT0603BRD078K06L
designator R?  ValueDisplayed: 8.06k  (hidden comment: RT0603BRD078K06L)
RES, 8.06 k, 0.1%, 0.1 W, 0603; Manufacturer: Yageo America; CompType: Resistor; Value: 8.06k; Res_ohm: 8060; Value_Code: 8k06; Tolerance_%: 0.1; Value2: 0.1W; VDC_V: 75; TempCo: 25 ppm/C; SizeArea_mm2: 1.28; SizeX_mm: 1.6; SizeY_mm: 0.8; SizeZ_mm: 1; EIA_Code: E192; U/M: EA; AEC Category: Q200
signal-integrity model Resistor
simulation model Resistor
footprint 0603
footprint 0603M
footprint 0603L
footprint 0603_HV
footprint 0603S
pins: 1, 2

## RT0603BRD078K16L
designator R?  ValueDisplayed: 8.16k  (hidden comment: RT0603BRD078K16L)
RES, 8.16 k, 0.1%, 0.1 W, 0603; Manufacturer: Yageo America; CompType: Resistor; Value: 8.16k; Res_ohm: 8160; Value_Code: 8k16; Tolerance_%: 0.1; Value2: 0.1W; VDC_V: 75; TempCo: 25 ppm/C; SizeArea_mm2: 1.28; SizeX_mm: 1.6; SizeY_mm: 0.8; SizeZ_mm: 1; EIA_Code: E192; U/M: EA; AEC Category: Q200
signal-integrity model Resistor
simulation model Resistor
footprint 0603
footprint 0603M
footprint 0603L
footprint 0603_HV
footprint 0603S
pins: 1, 2

## RT0603BRD078K25L
designator R?  ValueDisplayed: 8.25k  (hidden comment: RT0603BRD078K25L)
RES, 8.25 k, 0.1%, 0.1 W, 0603; Manufacturer: Yageo America; CompType: Resistor; Value: 8.25k; Res_ohm: 8250; Value_Code: 8k25; Tolerance_%: 0.1; Value2: 0.1W; VDC_V: 75; TempCo: 25 ppm/C; SizeArea_mm2: 1.28; SizeX_mm: 1.6; SizeY_mm: 0.8; SizeZ_mm: 1; EIA_Code: E192; U/M: EA; AEC Category: Q200
signal-integrity model Resistor
simulation model Resistor
footprint 0603
footprint 0603M
footprint 0603L
footprint 0603_HV
footprint 0603S
pins: 1, 2

## RT0603BRD078K35L
designator R?  ValueDisplayed: 8.35k  (hidden comment: RT0603BRD078K35L)
RES, 8.35 k, 0.1%, 0.1 W, 0603; Manufacturer: Yageo America; CompType: Resistor; Value: 8.35k; Res_ohm: 8350; Value_Code: 8k35; Tolerance_%: 0.1; Value2: 0.1W; VDC_V: 75; TempCo: 25 ppm/C; SizeArea_mm2: 1.28; SizeX_mm: 1.6; SizeY_mm: 0.8; SizeZ_mm: 1; EIA_Code: E192; U/M: EA; AEC Category: Q200
signal-integrity model Resistor
simulation model Resistor
footprint 0603
footprint 0603M
footprint 0603L
footprint 0603_HV
footprint 0603S
pins: 1, 2

## RT0603BRD078K45L
designator R?  ValueDisplayed: 8.45k  (hidden comment: RT0603BRD078K45L)
RES, 8.45 k, 0.1%, 0.1 W, 0603; Manufacturer: Yageo America; CompType: Resistor; Value: 8.45k; Res_ohm: 8450; Value_Code: 8k45; Tolerance_%: 0.1; Value2: 0.1W; VDC_V: 75; TempCo: 25 ppm/C; SizeArea_mm2: 1.28; SizeX_mm: 1.6; SizeY_mm: 0.8; SizeZ_mm: 1; EIA_Code: E192; U/M: EA; AEC Category: Q200
signal-integrity model Resistor
simulation model Resistor
footprint 0603
footprint 0603M
footprint 0603L
footprint 0603_HV
footprint 0603S
pins: 1, 2

## RT0603BRD078K56L
designator R?  ValueDisplayed: 8.56k  (hidden comment: RT0603BRD078K56L)
RES, 8.56 k, 0.1%, 0.1 W, 0603; Manufacturer: Yageo America; CompType: Resistor; Value: 8.56k; Res_ohm: 8560; Value_Code: 8k56; Tolerance_%: 0.1; Value2: 0.1W; VDC_V: 75; TempCo: 25 ppm/C; SizeArea_mm2: 1.28; SizeX_mm: 1.6; SizeY_mm: 0.8; SizeZ_mm: 1; EIA_Code: E192; U/M: EA; AEC Category: Q200
signal-integrity model Resistor
simulation model Resistor
footprint 0603
footprint 0603M
footprint 0603L
footprint 0603_HV
footprint 0603S
pins: 1, 2

## RT0603BRD078K66L
designator R?  ValueDisplayed: 8.66k  (hidden comment: RT0603BRD078K66L)
RES, 8.66 k, 0.1%, 0.1 W, 0603; Manufacturer: Yageo America; CompType: Resistor; Value: 8.66k; Res_ohm: 8660; Value_Code: 8k66; Tolerance_%: 0.1; Value2: 0.1W; VDC_V: 75; TempCo: 25 ppm/C; SizeArea_mm2: 1.28; SizeX_mm: 1.6; SizeY_mm: 0.8; SizeZ_mm: 1; EIA_Code: E192; U/M: EA; AEC Category: Q200
signal-integrity model Resistor
simulation model Resistor
footprint 0603
footprint 0603M
footprint 0603L
footprint 0603_HV
footprint 0603S
pins: 1, 2

## RT0603BRD078K76L
designator R?  ValueDisplayed: 8.76k  (hidden comment: RT0603BRD078K76L)
RES, 8.76 k, 0.1%, 0.1 W, 0603; Manufacturer: Yageo America; CompType: Resistor; Value: 8.76k; Res_ohm: 8760; Value_Code: 8k76; Tolerance_%: 0.1; Value2: 0.1W; VDC_V: 75; TempCo: 25 ppm/C; SizeArea_mm2: 1.28; SizeX_mm: 1.6; SizeY_mm: 0.8; SizeZ_mm: 1; EIA_Code: E192; U/M: EA; AEC Category: Q200
signal-integrity model Resistor
simulation model Resistor
footprint 0603
footprint 0603M
footprint 0603L
footprint 0603_HV
footprint 0603S
pins: 1, 2

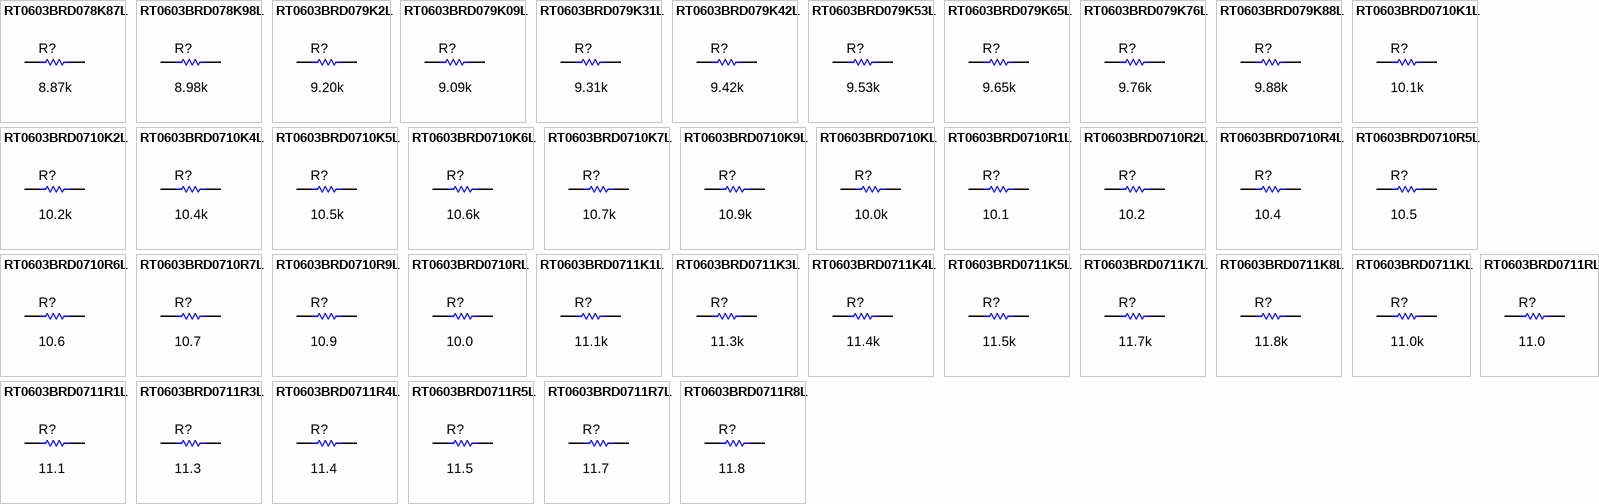
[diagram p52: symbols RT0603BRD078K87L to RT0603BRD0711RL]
